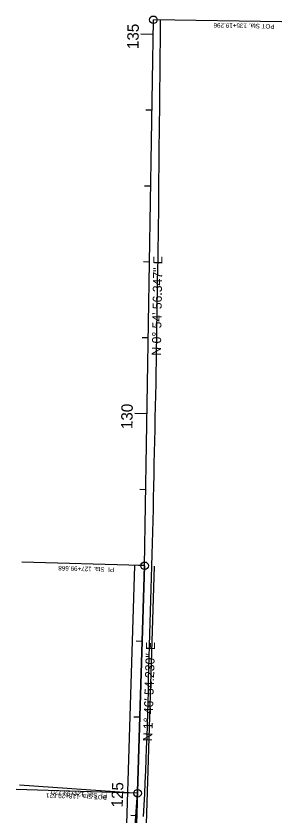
# Model space of a CAD drawing. Extents: x 1384498 to 1391279, y 1965973 to 1976560.
# Drawn here: x 1385045 to 1385395, y 1975277 to 1976331 of the extents above; entities that cross this region are included whole.
import ezdxf

# ---------------------------------------------------------------- set-up
doc = ezdxf.new("R2010")
doc.units = 0
for name, color, linetype in [('ALI_DESIGN_ML', 7, 'Continuous'), ('ALI_DESIGN_ML_LABELS', 7, 'Continuous'), ('ALI_DESIGN_ML_TICS', 7, 'Continuous'), ('Default', 7, 'Continuous'), ('S_EDGE_PAVEMENT', 7, 'Continuous'), ('TRANS_EOP_PAVED', 7, 'Continuous'), ('X_ALI_SURVEY_ML', 7, 'Continuous'), ('X_ALI_SURVEY_ML_CURVE_DATA', 7, 'Continuous'), ('X_ALI_SURVEY_ML_LABELS', 7, 'Continuous'), ('X_ALI_SURVEY_ML_STA', 7, 'Continuous'), ('X_ALI_SURVEY_ML_TICS', 7, 'Continuous'), ('X_TRANS_EOP', 7, 'Continuous')]:
    doc.layers.add(name, color=color, linetype=linetype)

msp = doc.modelspace()

# ---------------------------------------------------------------- linework, layer by layer
at = {"layer": 'ALI_DESIGN_ML'}
msp.add_line((1385191.5, 1974889.3), (1385213.8, 1975606.7), dxfattribs=at)
at = {"layer": 'ALI_DESIGN_ML_LABELS'}
msp.add_line((1385199.5, 1975307.1), (1385044.5, 1975311.9), dxfattribs=at)
msp.add_circle((1385204.5, 1975306.9), 5, dxfattribs=at)
at = {"layer": 'ALI_DESIGN_ML_TICS'}
msp.add_line((1385203.6, 1975277.3), (1385195.6, 1975277.5), dxfattribs=at)
at = {"layer": 'Default'}
msp.add_line((1385213.8, 1975606.7), (1385182.8, 1974610.2), dxfattribs=at)
at = {"layer": 'S_EDGE_PAVEMENT'}
msp.add_lwpolyline([(1385212.4, 1975276.4), (1385213.2, 1975291.3), (1385213.9, 1975306.2), (1385214.6, 1975321.3), (1385215.4, 1975336.4), (1385215.9, 1975351.4), (1385216.3, 1975366.4), (1385217, 1975381.4), (1385217.6, 1975396.6), (1385218.1, 1975411.6), (1385218.4, 1975426.6), (1385218.7, 1975441.6), (1385219, 1975456.6), (1385219.3, 1975471.6), (1385219.7, 1975486.3), (1385220.2, 1975501.3), (1385220.6, 1975516.5), (1385220.6, 1975516.5), (1385221.1, 1975531.5), (1385221.7, 1975546.5), (1385222.1, 1975561.5), (1385222.5, 1975576.4), (1385222.8, 1975591.4), (1385223.2, 1975606.4), (1385223.5, 1975621.4), (1385224, 1975636.5), (1385224.5, 1975651.5), (1385224.9, 1975666.5), (1385225.3, 1975681.5), (1385225.6, 1975696.4), (1385225.9, 1975711.4), (1385226.2, 1975726.4), (1385226.5, 1975741.4), (1385226.9, 1975756.5), (1385227.2, 1975771.5), (1385227.5, 1975786.5), (1385227.8, 1975801.5), (1385228.2, 1975816.5), (1385228.5, 1975831.4), (1385228.8, 1975846.5), (1385229.1, 1975861.5), (1385229.3, 1975876.5), (1385229.6, 1975891.5), (1385229.8, 1975906.5), (1385230, 1975921.5), (1385230.3, 1975936.5), (1385230.5, 1975951.5), (1385230.7, 1975966.5), (1385230.9, 1975981.5), (1385231.2, 1975996.6), (1385231.4, 1976011.5), (1385231.6, 1976026.5), (1385231.9, 1976041.5), (1385232.1, 1976056.5), (1385232.3, 1976071.5), (1385232.4, 1976086.5), (1385232.6, 1976101.5), (1385232.7, 1976116.5), (1385232.8, 1976131.5), (1385233, 1976146.5), (1385233.1, 1976161.5), (1385233.2, 1976176.6), (1385233.4, 1976191.6), (1385233.6, 1976206.6), (1385233.8, 1976221.5), (1385233.9, 1976236.5), (1385234.1, 1976251.5), (1385234.2, 1976266.5), (1385234.4, 1976281.5), (1385234.6, 1976296.5), (1385234.6, 1976311.7), (1385234.5, 1976326)], dxfattribs=at)
at = {"layer": 'TRANS_EOP_PAVED'}
for p, q in [((1385178.5, 1974889.7), (1385200.8, 1975607.1)), ((1385204.5, 1974888.9), (1385226.8, 1975606.3))]:
    msp.add_line(p, q, dxfattribs=at)
at = {"layer": 'X_ALI_SURVEY_ML'}
for p, q in [((1385213.8, 1975606.7), (1385225.3, 1976326.2)), ((1385204.5, 1975306.9), (1385213.8, 1975606.7)), ((1385193.4, 1975149.5), (1385204.5, 1975306.9))]:
    msp.add_line(p, q, dxfattribs=at)
at = {"layer": 'X_ALI_SURVEY_ML_LABELS'}
for p, q in [((1385394.6, 1976323.5), (1385225.3, 1976326.2)), ((1385208.8, 1975606.9), (1385052.1, 1975611.7)), ((1385199.5, 1975307.3), (1385049.3, 1975317.8))]:
    msp.add_line(p, q, dxfattribs=at)
for centre in [(1385225.3, 1976326.2), (1385213.8, 1975606.7), (1385204.5, 1975306.9)]:
    msp.add_circle(centre, 5, dxfattribs=at)
at = {"layer": 'X_ALI_SURVEY_ML_TICS'}
for p, q in [((1385225, 1976306.9), (1385209, 1976307.2)), ((1385223.4, 1976207), (1385215.4, 1976207.1)), ((1385221.8, 1976107), (1385213.8, 1976107.1)), ((1385220.2, 1976007), (1385212.2, 1976007.1)), ((1385218.6, 1975907), (1385210.6, 1975907.1)), ((1385217, 1975807), (1385201, 1975807.3)), ((1385215.4, 1975707), (1385207.4, 1975707.2)), ((1385213.8, 1975607), (1385205.8, 1975607.2)), ((1385210.7, 1975507.1), (1385202.7, 1975507.3)), ((1385207.6, 1975407.1), (1385199.6, 1975407.4)), ((1385204.5, 1975307.2), (1385188.5, 1975307.7))]:
    msp.add_line(p, q, dxfattribs=at)
at = {"layer": 'X_TRANS_EOP'}
msp.add_lwpolyline([(1385212.4, 1975276.4), (1385213.2, 1975291.3), (1385213.9, 1975306.2), (1385214.6, 1975321.3), (1385215.4, 1975336.4), (1385215.9, 1975351.4), (1385216.3, 1975366.4), (1385217, 1975381.4), (1385217.6, 1975396.6), (1385218.1, 1975411.6), (1385218.4, 1975426.6), (1385218.7, 1975441.6), (1385219, 1975456.6), (1385219.3, 1975471.6), (1385219.7, 1975486.3), (1385220.2, 1975501.3), (1385220.6, 1975516.5), (1385220.6, 1975516.5), (1385221.1, 1975531.5), (1385221.7, 1975546.5), (1385222.1, 1975561.5), (1385222.5, 1975576.4), (1385222.8, 1975591.4), (1385223.2, 1975606.4), (1385223.5, 1975621.4), (1385224, 1975636.5), (1385224.5, 1975651.5), (1385224.9, 1975666.5), (1385225.3, 1975681.5), (1385225.6, 1975696.4), (1385225.9, 1975711.4), (1385226.2, 1975726.4), (1385226.5, 1975741.4), (1385226.9, 1975756.5), (1385227.2, 1975771.5), (1385227.5, 1975786.5), (1385227.8, 1975801.5), (1385228.2, 1975816.5), (1385228.5, 1975831.4), (1385228.8, 1975846.5), (1385229.1, 1975861.5), (1385229.3, 1975876.5), (1385229.6, 1975891.5), (1385229.8, 1975906.5), (1385230, 1975921.5), (1385230.3, 1975936.5), (1385230.5, 1975951.5), (1385230.7, 1975966.5), (1385230.9, 1975981.5), (1385231.2, 1975996.6), (1385231.4, 1976011.5), (1385231.6, 1976026.5), (1385231.9, 1976041.5), (1385232.1, 1976056.5), (1385232.3, 1976071.5), (1385232.4, 1976086.5), (1385232.6, 1976101.5), (1385232.7, 1976116.5), (1385232.8, 1976131.5), (1385233, 1976146.5), (1385233.1, 1976161.5), (1385233.2, 1976176.6), (1385233.4, 1976191.6), (1385233.6, 1976206.6), (1385233.8, 1976221.5), (1385233.9, 1976236.5), (1385234.1, 1976251.5), (1385234.2, 1976266.5), (1385234.4, 1976281.5), (1385234.6, 1976296.5), (1385234.6, 1976311.7), (1385234.5, 1976326)], dxfattribs=at)

# ---------------------------------------------------------------- texts
at = {"layer": 'ALI_DESIGN_ML_LABELS'}
msp.add_text('POT Sta. 118+29.621', height=6, rotation=178.2183, dxfattribs=at).set_placement((1385164.4, 1975304.6))
at = {"layer": 'X_ALI_SURVEY_ML_CURVE_DATA'}
for s, rotation, p in [('N 0%%d 54\' 56.347" E', 89.0843, (1385235.2, 1975883.6)), ('N 1%%d 46\' 54.230" E', 88.2183, (1385223.6, 1975375.2))]:
    msp.add_text(s, height=12, rotation=rotation, dxfattribs=at).set_placement(p)
at = {"layer": 'X_ALI_SURVEY_ML_LABELS'}
for s, rotation, p in [('POT Sta. 135+19.296', 179.0843, (1385384.9, 1976320.6)), ('PI  Sta. 127+99.668', 178.2183, (1385173.7, 1975604.4)), ('PI  Sta. 124+99.720', 175.9677, (1385164.3, 1975306.2))]:
    msp.add_text(s, height=6, rotation=rotation, dxfattribs=at).set_placement(p)
at = {"layer": 'X_ALI_SURVEY_ML_STA'}
for s, rotation, p in [('135', 89.0843, (1385205.7, 1976287.5)), ('130', 89.0843, (1385197.7, 1975786.7)), ('125', 88.2183, (1385184.9, 1975288))]:
    msp.add_text(s, height=15, rotation=rotation, dxfattribs=at).set_placement(p)

doc.saveas('drawing.dxf')
